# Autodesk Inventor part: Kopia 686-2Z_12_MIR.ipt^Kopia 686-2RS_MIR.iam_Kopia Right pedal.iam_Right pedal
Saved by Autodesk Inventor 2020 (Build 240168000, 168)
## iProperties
Created: 2017-10
Part Number: Kopia 686-2Z_12_MIR.ipt^Kopia 686-2RS_MIR.iam_Kopia Right pedal.iam_Right pedal
Material: Ogólny
Document SubType Name: Modeling
Designer: Tomasz
Density: 1 g/cm^3
Appearance: Domyślna
Sending System: SolidWorks 2017
Last Author: Tomasz
Last Saved: 2017-10-01
Author: Tomasz
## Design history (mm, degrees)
